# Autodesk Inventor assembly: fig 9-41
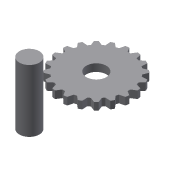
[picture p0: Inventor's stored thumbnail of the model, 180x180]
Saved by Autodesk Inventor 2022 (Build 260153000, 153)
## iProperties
Created: 2013-07
Part Number: fig 9-41
Document SubType Name: Assembly
Designer: CADCIM
Author: CADCIM
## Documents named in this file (3)
- D:\PROJECTS_2021\Resources\Part Files\c09_Inv_2022_prt\fig 9-42.iam
- D:\PROJECTS_2021\Resources\Part Files\c09_Inv_2022_prt\13.ipt
- D:\PROJECTS_2021\Resources\Part Files\c09_Inv_2022_prt\14.ipt
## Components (2 placed, 2 different names)
1. 13:1
2. 14:1
